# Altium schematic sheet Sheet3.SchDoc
size A3; SheetNumber: 1; SheetTotal: 2
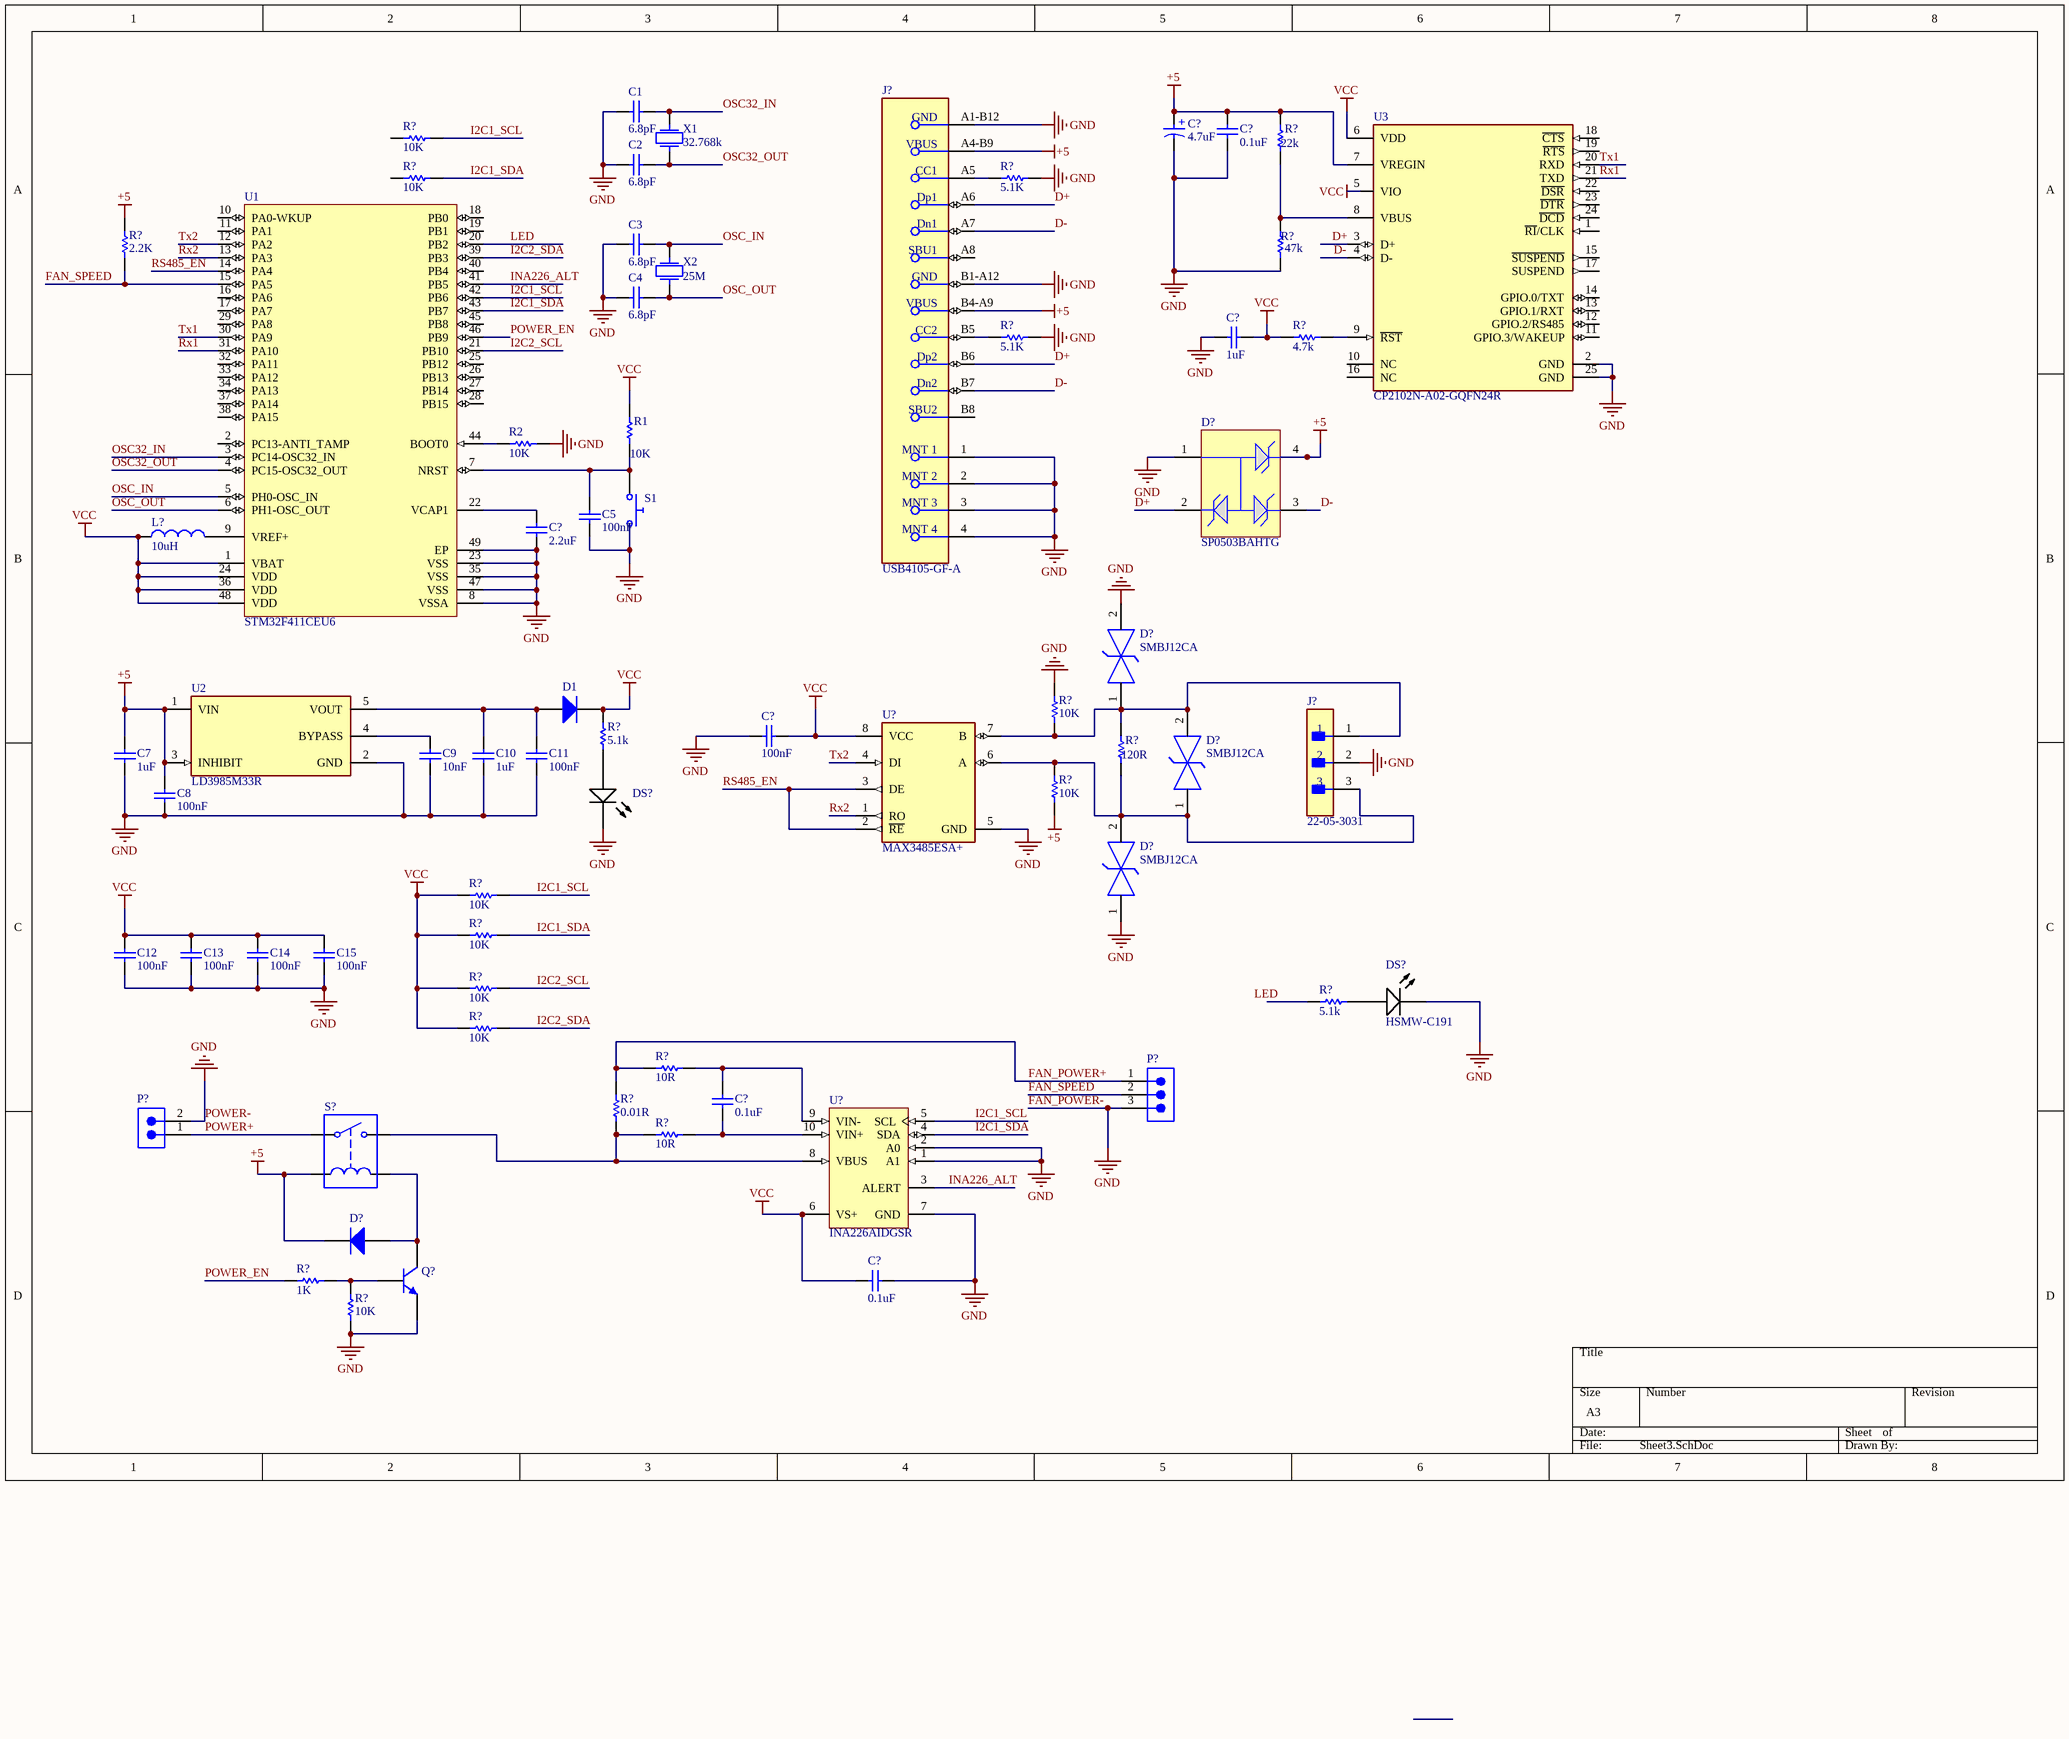
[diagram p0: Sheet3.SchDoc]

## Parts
(Parts that share a designator on the sheet are numbered #1, #2 ... from top to bottom, then left to right.)
C1  value 6.8pF  (hidden comment: Capacitor)
C2  value 6.8pF  (hidden comment: Capacitor)
C3  value 6.8pF  (hidden comment: Capacitor)
C4  value 6.8pF  (hidden comment: Capacitor)
C5  value 100nF  (hidden comment: Capacitor)
C7  value 1uF  (hidden comment: Capacitor)
C8  value 100nF  (hidden comment: Capacitor)
C9  value 10nF  (hidden comment: Capacitor)
C10  value 1uF  (hidden comment: Capacitor)
C11  value 100nF  (hidden comment: Capacitor)
C12  value 100nF  (hidden comment: Capacitor)
C13  value 100nF  (hidden comment: Capacitor)
C14  value 100nF  (hidden comment: Capacitor)
C15  value 100nF  (hidden comment: Capacitor)
C?#1  4.7uF  [WCAP-PT5H_D10H12.5]
C?#2  value 0.1uF  (hidden comment: Capacitor)
C?#3  value 1uF  (hidden comment: Capacitor)
C?#4  value 2.2uF  (hidden comment: Capacitor)
C?#5  value 100nF  (hidden comment: Capacitor)
C?#6  value 0.1uF  (hidden comment: Capacitor)
C?#7  value 0.1uF  (hidden comment: Capacitor)
D1  Diode  (value not drawn)
D?#1  SP0503BAHTG  [LFUS-SOT143-4_V]
D?#2  SMBJ12CA  [FP-SMBJ-MFG]
D?#3  SMBJ12CA  [FP-SMBJ-MFG]
D?#4  SMBJ12CA  [FP-SMBJ-MFG]
D?#5  Diode  (value not drawn)
DS?#1  (no value)  [AVAG-HSMW-C191_V]
DS?#2  HSMW-C191  [AVAG-HSMW-C191_V]
J?#1  USB4105-GF-A  [FP-USB4105-GF-A-MFG]
J?#2  22-05-3031  [FP-22-05-3031-MFG]
L?  value 10uH  (hidden comment: Inductor)
P?#1  (no value)  [648103131822]
P?#2  (no value)  [620302124022]
Q?  Bipolar NPN 3 Pins Transistor Gummel-Poon Model  (value not drawn)
R1  value 10K  (hidden comment: Resistor)
R2  value 10K  (hidden comment: Resistor)
R?#1  value 10K  (hidden comment: Resistor)
R?#2  value 22k  (hidden comment: Resistor)
R?#3  value 10K  (hidden comment: Resistor)
R?#4  value 5.1K  (hidden comment: Resistor)
R?#5  value 2.2K  (hidden comment: Resistor)
R?#6  value 47k  (hidden comment: Resistor)
R?#7  value 5.1K  (hidden comment: Resistor)
R?#8  value 4.7k  (hidden comment: Resistor)
R?#9  value 10K  (hidden comment: Resistor)
R?#10  value 5.1k  (hidden comment: Resistor)
R?#11  value 120R  (hidden comment: Resistor)
R?#12  value 10K  (hidden comment: Resistor)
R?#13  value 10K  (hidden comment: Resistor)
R?#14  value 10K  (hidden comment: Resistor)
R?#15  value 10K  (hidden comment: Resistor)
R?#16  value 5.1k  (hidden comment: Resistor)
R?#17  value 10K  (hidden comment: Resistor)
R?#18  value 10R  (hidden comment: Resistor)
R?#19  value 0.01R  (hidden comment: Resistor)
R?#20  value 10R  (hidden comment: Resistor)
R?#21  value 1K  (hidden comment: Resistor)
R?#22  value 10K  (hidden comment: Resistor)
S1  Push Button Normally Opened  (value not drawn)
S?  Single-Pole, Single-Throw Normally Opened Relay  (value not drawn)
U1  STM32F411CEU6  [STM-UFQFPN48_L]
U2  LD3985M33R  [FP-SOT23-5L-7049676-MFG]
U3  CP2102N-A02-GQFN24R  [FP-CP2102N-A02-GQFN24R-MFG]
U?#1  MAX3485ESA+  [FP-S8-5-MFG]
U?#2  INA226AIDGSR  [DGS0010A_L]
X1  F0: 32.768k  (hidden comment: Crystal)
X2  F0: 25M  (hidden comment: Crystal)

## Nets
+5: C7.2 C8.2 C?#1.1(P) C?#2.1 D?#1.4 D?#5.2(K) J?#1.A4-B9(VBUS) J?#1.B4-A9(VBUS) R?#2.2 R?#5.2 R?#12.1 S?.3 U2.1(VIN) U2.3(INHIBIT) U3.7(VREGIN)
FAN_POWER-: C1.1 C2.1 C3.1 C4.1 C5.1 C7.1 C8.1 C9.1 C10.1 C11.1 C12.1 C13.1 C14.1 C15.1 C?#1.2(N) C?#2.2 C?#3.2 C?#4.1 C?#5.2 C?#7.1 D?#1.1 D?#2.2 D?#4.1 DS?#1.2(K) DS?#2.2(K) J?#1.1(MNT_1) J?#1.2(MNT_2) J?#1.3(MNT_3) J?#1.4(MNT_4) J?#1.A1-B12(GND) J?#1.B1-A12(GND) J?#2.2 P?#1.3 P?#2.2 Q?.3(E) R2.2 R?#4.2 R?#6.1 R?#7.2 R?#9.2 R?#22.1 S1.2 U1.8(VSSA) U1.23(VSS) U1.35(VSS) U1.47(VSS) U1.49(EP) U2.2(GND) U3.2(GND) U3.25(GND) U?#1.5(GND) U?#2.1(A1) U?#2.2(A0) U?#2.7(GND)  [also labelled GND, POWER-]
VCC: C12.2 C13.2 C14.2 C15.2 C?#3.1 C?#5.1 C?#7.2 D1.2(K) L?.1 R1.2 R?#8.1 R?#10.2 R?#13.2 R?#14.2 R?#15.2 R?#17.2 U1.1(VBAT) U1.24(VDD) U1.36(VDD) U1.48(VDD) U3.5(VIO) U3.6(VDD) U?#1.8(VCC) U?#2.6(VS+)
D+: D?#1.2 J?#1.A6(Dp1) J?#1.B6(Dp2) U3.3(D+)
D-: D?#1.3 J?#1.A7(Dn1) J?#1.B7(Dn2) U3.4(D-)
FAN_POWER+: P?#1.1 R?#18.2 R?#19.1
FAN_SPEED: P?#1.2 R?#5.1 U1.15(PA5)
I2C1_SCL: R?#1.1 R?#13.1 U1.42(PB6) U?#2.5(SCL)
I2C1_SDA: R?#3.1 R?#14.1 U1.43(PB7) U?#2.4(SDA)
I2C2_SCL: R?#15.1 U1.21(PB10)
I2C2_SDA: R?#17.1 U1.39(PB3)
INA226_ALT: U1.41(PB5) U?#2.3(ALERT)
LED: U1.20(PB2)
OSC32_IN: C1.2 U1.3(PC14-OSC32_IN) X1.2
OSC32_OUT: C2.2 U1.4(PC15-OSC32_OUT) X1.1
OSC_IN: C3.2 U1.5(PH0-OSC_IN) X2.2
OSC_OUT: C4.2 U1.6(PH1-OSC_OUT) X2.1
POWER+: P?#2.1 S?.1
POWER_EN: R?#21.1 U1.46(PB9)
RS485_EN: U1.14(PA4) U?#1.2(~{RE}) U?#1.3(DE)
Rx1: U1.31(PA10) U3.21(TXD)
Rx2: U1.13(PA3) U?#1.1(RO)
Tx1: U1.30(PA9) U3.20(RXD)
Tx2: U1.12(PA2) U?#1.4(DI)
NetC5_2: C5.2 R1.1 S1.1 U1.7(NRST)
NetC9_2: C9.2 U2.4(BYPASS)
NetC10_2: C10.2 C11.2 D1.1(A) U2.5(VOUT)
NetC?#4_2: C?#4.2 U1.22(VCAP1)
NetC?#6_1: C?#6.1 R?#20.1 U?#2.10(VIN+)
NetC?#6_2: C?#6.2 R?#18.1 U?#2.9(VIN-)
NetD?#2_1: D?#2.1 D?#3.2 J?#2.1 R?#9.1 R?#11.2 U?#1.7(B)
NetD?#3_1: D?#3.1 D?#4.2 J?#2.3 R?#11.1 R?#12.2 U?#1.6(A)
NetD?#5_1: D?#5.1(A) Q?.1(C) S?.4
NetDS?#1_1: DS?#1.1(A) R?#10.1
NetDS?#2_1: DS?#2.1(A) R?#16.2
NetJ?#1_A5: J?#1.A5(CC1) R?#4.1
NetJ?#1_B5: J?#1.B5(CC2) R?#7.1
NetL?_2: L?.2 U1.9(VREF+)
NetQ?_2: Q?.2(B) R?#21.2 R?#22.2
NetR2_1: R2.1 U1.44(BOOT0)
NetR?#2_1: R?#2.1 R?#6.2 U3.8(VBUS)
NetR?#8_2: R?#8.2 U3.9(~{RST})
NetR?#19_2: R?#19.2 R?#20.2 S?.2 U?#2.8(VBUS)

Not connected (* = marked no-connect by the designer): J?#1 A8(SBU1) B8(SBU2); R?#1 2; R?#3 2; R?#16 1; U1 2(PC13-ANTI_TAMP) 10(PA0-WKUP) 11(PA1) 16(PA6) 17(PA7) 18(PB0) 19(PB1) 25(PB12) 26(PB13) 27(PB14) 28(PB15) 29(PA8) 32(PA11) 33(PA12) 34(PA13) 37(PA14) 38(PA15) 40(PB4) 45(PB8); U3 1(~{RI}/CLK) 10(NC) 11(GPIO.3/WAKEUP) 12(GPIO.2/RS485) 13(GPIO.1/RXT) 14(GPIO.0/TXT) 15(~{SUSPEND}) 16(NC) 17(SUSPEND) 18(~{CTS}) 19(~{RTS}) 22(~{DSR}) 23(~{DTR}) 24(~{DCD})

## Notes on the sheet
- Labels drawn without touching a wire or pin: LED

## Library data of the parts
C1-C5 C7-C15 C?#2-C?#7 = Capacitor: SimulationGenericComponent: True
C?#1 = CMP-03913-54202637-1: 870235175007 WCAP-PT5H Aluminum Polymer Capacitors; Leakage Current: 756µA; Voltage Rating: 6.3V; Ripple Current: 6.64A; Life (Hours): 5000hours; Pitch: 5mm; Capacitance: 1.2mF; Tolerance: 20%; ESR (Equivalent Series Resistance): 7mΩ; Polarity: Polar
D1 D?#5 = Diode: AF: 1; BV: 0; BV_MAX: 1e99; EG: 1.11; FC: 0.5; IBV: 0.001; ISR: 1e-14; MJSW: 0.33; NTUN: 30; TNOM: 27; XTI: 3; SimulationGenericComponent: True
D?#1 = CMP-2000-05191-1: TVS Diode Array, 30 pF, 30 KV, -40 to 85 degC, 4-Pin SOT143, RoHS, Tape and Reel; Manufacturer: Littelfuse; Direction Type: Uni-Directional; Product Height (mm): 1.05mm; Leakage Current (Max): 0.1uA; Clamping Voltage (Max): 8V; Reverse Stand-off Voltage: 5.5(Min)V; Configuration: Triple; Working Voltage: 5.5V; Product Length (mm): 3.04mm; Working Voltage (Max): 5.5V(Min); Capacitance Value: 30pF; Rad Hardened: No; Number of Elements: 3; Product Depth (mm): 1.4mm
D?#2-D?#4 = CMP-08607-000016-1: TVS DIODE 12V 19.9V DO214AA; Manufacturer: Littelfuse Inc; Breakdown Voltage: 13.3V; Max Junction Temp: +150°C; Direction: Bidirectional; Number Of Channels: 1; Peak Pulse Current: 30.2A; Peak Pulse Power: 600W
DS?#1 DS?#2 = CMP-007-00016-2: LED Uni-Color White, 78 mW, 20 mA, -40 to 85 degC, 2-Pin SMD, RoHS, Tape and Reel; Manufacturer: Avago; Power: 78mW; Lens Style: Diffused; Luminous Intensity: 200mcd; Forward Voltage: 3.6V; Viewing Angle: 140degrees; Forward Current: 20mA
J?#1 = CMP-245163-000001-1: CONN RCPT USB2.0 TYPEC 5A; Manufacturer: GCT; Voltage Rating: 20V; Is Female: yes; Current Rating: 5/6.25/1.25/0.25A; Number Of Contacts: 16; Conn Orientation: Right Angle
J?#2 = CMP-04776-000253-1: CONN HEADER R/A 3POS 2.54MM; Number of Positions: 3; Max Current Rating: 4A; Contact Resistance: 10mR; Voltage Rating (DC): 250V; Gender: Male; Approvals: UL; Insulation Resistance: 50GR; Glow Wire Compliant: Non-compliant
L? = Inductor: SimulationGenericComponent: True
P?#1 = CMP-1502-00731-2: NexarPartId: 18818252; Pitch: 1.5mm; Contact Resistance: 20mΩ; Insulation Resistance: 500MΩ; Current Rating: 1A; Operating Supply Voltage: 50V; Number of Contacts: 3; Connector Type: Male Pin; Insulation: Insulated; Gender: Male
P?#2 = CMP-1502-00660-2: NexarPartId: 18818242; Insulation: Insulated; Connector Type: Male Pin; Pitch: 2mm; Insulation Resistance: 1GΩ; Gender: Male; Voltage Rating: 125V; Number of Positions: 2; Contact Resistance: 20mΩ; Operating Supply Voltage: 100V; Current Rating: 2A
Q? = BJT NPN_GP: SimulationGenericComponent: True; BF: 100; AF: 0; BR: 1; EG: 1.11; FC: 0.5; IS: 1e-16; MJC: 0.33; NC: 2; NE: 1.5; TNOM: 27; VBC_MAX: 1e99; VJC: 0.75; XTI: 3
R1 R2 R?#1-R?#22 = Resistor: TC1: 0; SimulationGenericComponent: True
S1 = Push Button NO: closed: 0; Rclosed: 1m; Ropen: 1Meg; SimulationGenericComponent: True
S? = SPST Relay NO: L_C: 1u; R_C: 100; RON: 1; ROFF: 1e12; ION: 1m; IOFF: 0; SimulationGenericComponent: True
U1 = CMP-0243-00165-1: ARM Cortex-M4 32-bit MCU+FPU, 512 KB Flash, 128 KB RAM, 36 I/Os, 48-Pin UFQFPN, -40 to 85 degC, Tray; Operating Frequency(F) (Processor speed) (MHz): 100; FLASH Size (Prog) (kB): 512; Internal RAM Size (kB): 128; I/Os (High Current): 36; Supply Voltage(Vcc) min (V): 1.7
U2 = CMP-0244-00328-3: NexarPartId: 526998; Min Output Voltage: 3.3V; Min Input Voltage: 2.5V; Max Junction Temperature (Tj): 125°C; Min Current Limit: 300mA; Input Bias Current: 85µA; Max Supply Voltage: 6V; Quiescent Current: 150µA; Max Output Current: 150mA; Number of Channels: 1; Output Type: Fixed; Output Voltage Accuracy: 2%; Polarity: Positive; Dropout Voltage: 60mV
U3 = CMP-08107-000009-2: IC USB TO UART BRIDGE QFN24; Manufacturer Lifecycle Status: FULL PRODUCTION; NexarPartId: 99772192; Max Junction Temperature (Tj): 105°C; Min Supply Voltage: 1.71V; Max Supply Voltage: 3.6V; Number of Digital IO: 4; Interface: I2C, RS-485, UART, USB
U?#1 = CMP-05679-000020-1: IC TXRX RS485/422 10MBPS 8SOIC; Manufacturer: Maxim Integrated; Nominal Supply Current: 0.95-1.1mA; Data Rate: 10Mbits/s; Min Supply Voltage: 3V; Interface: RS-485,RS-422; Number Of Transmitters: 1; Max Supply Voltage: 3.6V; Max Junction Temp: +160°C; Standoff Height: 0.1mm; Simplex Duplex: Half Duplex
U?#2 = CMP-0704-00058-2: High-Side Measurement, Bi-Directional Current / Power Monitor with I2C Interface, 2.7 to 5.5 V, -40 to 125 degC, 10-pin SOP (DGS10), Green (RoHS & no Sb/Br); Vs(Max)(V): 5.5; CMRR(Min)(dB): 126; Rating: Catalog; Input Offset (+/-)(Max)(uV): 10; Small-Signal Bandwidth(Typ)(MHz): 0.007; Input Offset Drift (+/-)(Max)(uV/Degrees Celsius): 0.1; Common Mode Range(Max)(V): 36; Gain(V/V): 1; SubFamily: Current Shunt Monitor; Quiescent Current (+/-)(Typ)(mA): 0.33; Vs(Min)(V): 2.7; Common Mode Range(Min)(V): 0
X1 X2 = Crystal: R: 500; Q: 50K; SimulationGenericComponent: True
